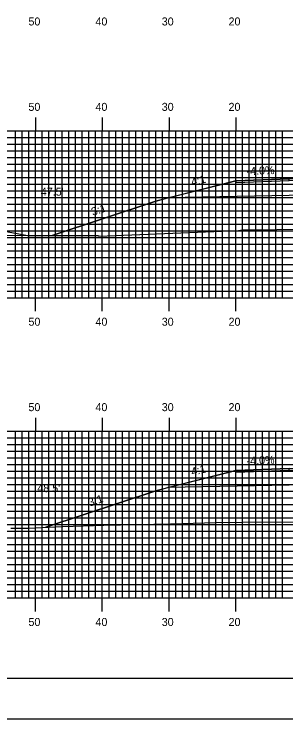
# Model space of a CAD drawing. Extents: x 1822785 to 1823129, y 442591 to 442811.
# Drawn here: x 1822898.1 to 1822938.8, y 442590.5 to 442696.2 of the extents above; entities that cross this region are included whole.
import ezdxf

# ---------------------------------------------------------------- set-up
doc = ezdxf.new("R2010")
doc.units = 0
for name, color, linetype in [('ANNOTATION', 7, 'Continuous'), ('BORDER', 7, 'Continuous'), ('D_Roadway_Centerline', 7, 'Continuous'), ('D_Roadway_Edge_Shoulder', 7, 'Continuous'), ('D_Roadway_SlopeLines', 7, 'Continuous'), ('D_Roadway_SubGrade', 7, 'Continuous'), ('D_Text_Standard', 7, 'Continuous'), ('H_V ANNOTATION', 7, 'Continuous'), ('MAJOR', 7, 'Continuous'), ('MINOR', 7, 'Continuous'), ('PLOT BOUNDARY', 7, 'Continuous'), ('S_Roadway_Centerline', 7, 'Continuous')]:
    doc.layers.add(name, color=color, linetype=linetype)

msp = doc.modelspace()

# ---------------------------------------------------------------- linework, layer by layer
at = {"layer": 'ANNOTATION'}
msp.add_line((1822903.76, 442662.99), (1822811.28, 442662.53), dxfattribs=at)
at = {"layer": 'BORDER'}
msp.add_lwpolyline([(1822801.68, 442596.67), (1823121.68, 442596.67), (1823121.68, 442806.67), (1822801.68, 442806.67)], close=True, dxfattribs=at)
at = {"layer": 'D_Roadway_Centerline'}
for points in [[(1822903.76, 442662.99), (1822919.28, 442668.16), (1822921.11, 442668.62), (1822931.28, 442671.16), (1822939.28, 442671.48), (1822951.28, 442671.72), (1822963.28, 442671.48), (1822971.28, 442671.16), (1822981.46, 442668.62), (1822998.04, 442664.47)], [(1822902.83, 442619.27), (1822919.28, 442624.75), (1822921.11, 442625.21), (1822931.28, 442627.75), (1822939.28, 442628.07), (1822951.28, 442628.31), (1822963.28, 442628.07), (1822971.28, 442627.75), (1822981.46, 442625.21), (1823001.12, 442620.29)]]:
    msp.add_lwpolyline(points, dxfattribs=at)
at = {"layer": 'D_Roadway_Edge_Shoulder'}
for points in [[(1822939.28, 442671.48), (1822931.28, 442671.16), (1822931.28, 442670.91), (1822939.28, 442671.23)], [(1822939.28, 442628.07), (1822931.28, 442627.75), (1822931.28, 442627.5), (1822939.28, 442627.82)]]:
    msp.add_lwpolyline(points, close=True, dxfattribs=at)
at = {"layer": 'D_Roadway_SlopeLines'}
for points in [[(1822931.28, 442671.16), (1822919.28, 442668.16), (1822903.76, 442662.99)], [(1822931.28, 442627.75), (1822919.28, 442624.75), (1822902.83, 442619.27)]]:
    msp.add_lwpolyline(points, dxfattribs=at)
at = {"layer": 'D_Roadway_SubGrade'}
for points in [[(1822939.28, 442668.98), (1822921.11, 442668.62), (1822931.28, 442671.16), (1822931.28, 442670.91), (1822939.28, 442671.23), (1822951.28, 442671.47), (1822963.28, 442671.23), (1822971.28, 442670.91), (1822971.28, 442671.16), (1822981.46, 442668.62), (1822963.28, 442668.98), (1822951.28, 442669.22)], [(1822939.28, 442625.57), (1822921.11, 442625.21), (1822931.28, 442627.75), (1822931.28, 442627.5), (1822939.28, 442627.82), (1822951.28, 442628.06), (1822963.28, 442627.82), (1822971.28, 442627.5), (1822971.28, 442627.75), (1822981.46, 442625.21), (1822963.28, 442625.57), (1822951.28, 442625.81)]]:
    msp.add_lwpolyline(points, close=True, dxfattribs=at)
at = {"layer": 'MAJOR'}
for p, q in [((1822901.28, 442680.67), (1822901.28, 442678.67)), ((1822911.28, 442680.67), (1822911.28, 442678.67)), ((1822921.28, 442680.67), (1822921.28, 442678.67)), ((1822931.28, 442680.67), (1822931.28, 442678.67)), ((1822811.28, 442678.67), (1823091.28, 442678.67)), ((1822811.28, 442678.67), (1823091.28, 442678.67)), ((1822901.28, 442653.67), (1822901.28, 442678.67)), ((1822911.28, 442653.67), (1822911.28, 442678.67)), ((1822921.28, 442653.67), (1822921.28, 442678.67)), ((1822931.28, 442653.67), (1822931.28, 442678.67)), ((1822811.28, 442673.67), (1823091.28, 442673.67)), ((1822811.28, 442668.67), (1823091.28, 442668.67)), ((1822811.28, 442663.67), (1823091.28, 442663.67)), ((1822811.28, 442658.67), (1823091.28, 442658.67)), ((1822811.28, 442653.67), (1823091.28, 442653.67)), ((1822811.28, 442653.67), (1823091.28, 442653.67)), ((1822901.28, 442651.66), (1822901.28, 442653.67)), ((1822911.28, 442651.66), (1822911.28, 442653.67)), ((1822921.28, 442651.66), (1822921.28, 442653.67)), ((1822931.28, 442651.66), (1822931.28, 442653.67)), ((1822901.28, 442635.67), (1822901.28, 442633.67)), ((1822911.28, 442635.67), (1822911.28, 442633.67)), ((1822921.28, 442635.67), (1822921.28, 442633.67)), ((1822931.28, 442635.67), (1822931.28, 442633.67)), ((1822811.28, 442633.67), (1823091.28, 442633.67)), ((1822811.28, 442633.67), (1823091.28, 442633.67)), ((1822901.28, 442608.67), (1822901.28, 442633.67)), ((1822911.28, 442608.67), (1822911.28, 442633.67)), ((1822921.28, 442608.67), (1822921.28, 442633.67)), ((1822931.28, 442608.67), (1822931.28, 442633.67)), ((1822811.28, 442628.67), (1823091.28, 442628.67)), ((1822811.28, 442623.67), (1823091.28, 442623.67)), ((1822811.28, 442618.67), (1823091.28, 442618.67)), ((1822811.28, 442613.67), (1823091.28, 442613.67)), ((1822811.28, 442608.67), (1823091.28, 442608.67)), ((1822811.28, 442608.67), (1823091.28, 442608.67)), ((1822901.28, 442606.66), (1822901.28, 442608.67)), ((1822911.28, 442606.66), (1822911.28, 442608.67)), ((1822921.28, 442606.66), (1822921.28, 442608.67)), ((1822931.28, 442606.66), (1822931.28, 442608.67))]:
    msp.add_line(p, q, dxfattribs=at)
at = {"layer": 'MINOR'}
for p, q in [((1822898.28, 442653.67), (1822898.28, 442678.67)), ((1822899.28, 442653.67), (1822899.28, 442678.67)), ((1822900.28, 442653.67), (1822900.28, 442678.67)), ((1822902.28, 442653.67), (1822902.28, 442678.67)), ((1822903.28, 442653.67), (1822903.28, 442678.67)), ((1822904.28, 442653.67), (1822904.28, 442678.67)), ((1822905.28, 442653.67), (1822905.28, 442678.67)), ((1822906.28, 442653.67), (1822906.28, 442678.67)), ((1822907.28, 442653.67), (1822907.28, 442678.67)), ((1822908.28, 442653.67), (1822908.28, 442678.67)), ((1822909.28, 442653.67), (1822909.28, 442678.67)), ((1822910.28, 442653.67), (1822910.28, 442678.67)), ((1822912.28, 442653.67), (1822912.28, 442678.67)), ((1822913.28, 442653.67), (1822913.28, 442678.67)), ((1822914.28, 442653.67), (1822914.28, 442678.67)), ((1822915.28, 442653.67), (1822915.28, 442678.67)), ((1822916.28, 442653.67), (1822916.28, 442678.67)), ((1822917.28, 442653.67), (1822917.28, 442678.67)), ((1822918.28, 442653.67), (1822918.28, 442678.67)), ((1822919.28, 442653.67), (1822919.28, 442678.67)), ((1822920.28, 442653.67), (1822920.28, 442678.67)), ((1822922.28, 442653.67), (1822922.28, 442678.67)), ((1822923.28, 442653.67), (1822923.28, 442678.67)), ((1822924.28, 442653.67), (1822924.28, 442678.67)), ((1822925.28, 442653.67), (1822925.28, 442678.67)), ((1822926.28, 442653.67), (1822926.28, 442678.67)), ((1822927.28, 442653.67), (1822927.28, 442678.67)), ((1822928.28, 442653.67), (1822928.28, 442678.67)), ((1822929.28, 442653.67), (1822929.28, 442678.67)), ((1822930.28, 442653.67), (1822930.28, 442678.67)), ((1822932.28, 442653.67), (1822932.28, 442678.67)), ((1822933.28, 442653.67), (1822933.28, 442678.67)), ((1822934.28, 442653.67), (1822934.28, 442678.67)), ((1822935.28, 442653.67), (1822935.28, 442678.67)), ((1822936.28, 442653.67), (1822936.28, 442678.67)), ((1822937.28, 442653.67), (1822937.28, 442678.67)), ((1822938.28, 442653.67), (1822938.28, 442678.67)), ((1822811.28, 442677.67), (1823091.28, 442677.67)), ((1822811.28, 442676.67), (1823091.28, 442676.67)), ((1822811.28, 442675.67), (1823091.28, 442675.67)), ((1822811.28, 442674.67), (1823091.28, 442674.67)), ((1822811.28, 442672.67), (1823091.28, 442672.67)), ((1822811.28, 442671.67), (1823091.28, 442671.67)), ((1822811.28, 442670.67), (1823091.28, 442670.67)), ((1822811.28, 442669.67), (1823091.28, 442669.67)), ((1822811.28, 442667.67), (1823091.28, 442667.67)), ((1822811.28, 442666.67), (1823091.28, 442666.67)), ((1822811.28, 442665.67), (1823091.28, 442665.67)), ((1822811.28, 442664.67), (1823091.28, 442664.67)), ((1822811.28, 442662.67), (1823091.28, 442662.67)), ((1822811.28, 442661.67), (1823091.28, 442661.67)), ((1822811.28, 442660.67), (1823091.28, 442660.67)), ((1822811.28, 442659.67), (1823091.28, 442659.67)), ((1822811.28, 442657.67), (1823091.28, 442657.67)), ((1822811.28, 442656.67), (1823091.28, 442656.67)), ((1822811.28, 442655.67), (1823091.28, 442655.67)), ((1822811.28, 442654.67), (1823091.28, 442654.67)), ((1822898.28, 442608.67), (1822898.28, 442633.67)), ((1822899.28, 442608.67), (1822899.28, 442633.67)), ((1822900.28, 442608.67), (1822900.28, 442633.67)), ((1822902.28, 442608.67), (1822902.28, 442633.67)), ((1822903.28, 442608.67), (1822903.28, 442633.67)), ((1822904.28, 442608.67), (1822904.28, 442633.67)), ((1822905.28, 442608.67), (1822905.28, 442633.67)), ((1822906.28, 442608.67), (1822906.28, 442633.67)), ((1822907.28, 442608.67), (1822907.28, 442633.67)), ((1822908.28, 442608.67), (1822908.28, 442633.67)), ((1822909.28, 442608.67), (1822909.28, 442633.67)), ((1822910.28, 442608.67), (1822910.28, 442633.67)), ((1822912.28, 442608.67), (1822912.28, 442633.67)), ((1822913.28, 442608.67), (1822913.28, 442633.67)), ((1822914.28, 442608.67), (1822914.28, 442633.67)), ((1822915.28, 442608.67), (1822915.28, 442633.67)), ((1822916.28, 442608.67), (1822916.28, 442633.67)), ((1822917.28, 442608.67), (1822917.28, 442633.67)), ((1822918.28, 442608.67), (1822918.28, 442633.67)), ((1822919.28, 442608.67), (1822919.28, 442633.67)), ((1822920.28, 442608.67), (1822920.28, 442633.67)), ((1822922.28, 442608.67), (1822922.28, 442633.67)), ((1822923.28, 442608.67), (1822923.28, 442633.67)), ((1822924.28, 442608.67), (1822924.28, 442633.67)), ((1822925.28, 442608.67), (1822925.28, 442633.67)), ((1822926.28, 442608.67), (1822926.28, 442633.67)), ((1822927.28, 442608.67), (1822927.28, 442633.67)), ((1822928.28, 442608.67), (1822928.28, 442633.67)), ((1822929.28, 442608.67), (1822929.28, 442633.67)), ((1822930.28, 442608.67), (1822930.28, 442633.67)), ((1822932.28, 442608.67), (1822932.28, 442633.67)), ((1822933.28, 442608.67), (1822933.28, 442633.67)), ((1822934.28, 442608.67), (1822934.28, 442633.67)), ((1822935.28, 442608.67), (1822935.28, 442633.67)), ((1822936.28, 442608.67), (1822936.28, 442633.67)), ((1822937.28, 442608.67), (1822937.28, 442633.67)), ((1822938.28, 442608.67), (1822938.28, 442633.67)), ((1822811.28, 442632.67), (1823091.28, 442632.67)), ((1822811.28, 442631.67), (1823091.28, 442631.67)), ((1822811.28, 442630.67), (1823091.28, 442630.67)), ((1822811.28, 442629.67), (1823091.28, 442629.67)), ((1822811.28, 442627.67), (1823091.28, 442627.67)), ((1822811.28, 442626.67), (1823091.28, 442626.67)), ((1822811.28, 442625.67), (1823091.28, 442625.67)), ((1822811.28, 442624.67), (1823091.28, 442624.67)), ((1822811.28, 442622.67), (1823091.28, 442622.67)), ((1822811.28, 442621.67), (1823091.28, 442621.67)), ((1822811.28, 442620.67), (1823091.28, 442620.67)), ((1822811.28, 442619.67), (1823091.28, 442619.67)), ((1822811.28, 442617.67), (1823091.28, 442617.67)), ((1822811.28, 442616.67), (1823091.28, 442616.67)), ((1822811.28, 442615.67), (1823091.28, 442615.67)), ((1822811.28, 442614.67), (1823091.28, 442614.67)), ((1822811.28, 442612.67), (1823091.28, 442612.67)), ((1822811.28, 442611.67), (1823091.28, 442611.67)), ((1822811.28, 442610.67), (1823091.28, 442610.67)), ((1822811.28, 442609.67), (1823091.28, 442609.67))]:
    msp.add_line(p, q, dxfattribs=at)
at = {"layer": 'PLOT BOUNDARY'}
msp.add_lwpolyline([(1822785.5, 442590.55), (1823125.5, 442590.55), (1823125.5, 442810.55), (1822785.5, 442810.55)], close=True, dxfattribs=at)
at = {"layer": 'S_Roadway_Centerline'}
for points in [[(1822896.35, 442663.67), (1822899.55, 442663.09), (1822900.08, 442663.01), (1822900.21, 442663), (1822901.21, 442662.99), (1822910.69, 442662.97), (1822910.77, 442662.9), (1822931.67, 442663.75), (1822932.25, 442663.82), (1822933.55, 442663.86), (1822945.21, 442664.01), (1822948.74, 442664.06), (1822949.55, 442664.07), (1822962.02, 442664.3), (1822966.67, 442664.36), (1822975.75, 442664.19), (1822983.42, 442664.35), (1822988.9, 442664.44), (1823000.16, 442664.48), (1823006.05, 442664.59)], [(1822897.57, 442619.14), (1822900.15, 442619.12), (1822905.36, 442619.4), (1822911.52, 442619.6), (1822921.49, 442619.78), (1822928.3, 442619.99), (1822932.35, 442620.05), (1822945.24, 442620.07), (1822949.76, 442620.06), (1822959.75, 442620.04), (1822962.6, 442620.07), (1822973.3, 442620.28), (1822979.45, 442620.33), (1822990.81, 442620.28), (1822996.89, 442620.26), (1823000.09, 442620.26), (1823013.45, 442620.66)]]:
    msp.add_lwpolyline(points, dxfattribs=at)

# ---------------------------------------------------------------- texts
at = {"layer": 'ANNOTATION'}
for s, rotation, p in [('-4.0%', 2.2906, (1822932.91, 442672.03)), ('4:1', 14.0362, (1822924.73, 442670.39)), ('3:1', 18.4348, (1822909.86, 442665.93)), ('-4.0%', 2.2906, (1822932.91, 442628.62)), ('4:1', 14.0362, (1822924.73, 442626.97)), ('3:1', 18.4348, (1822909.4, 442622.36))]:
    msp.add_text(s, height=1.2, rotation=rotation, dxfattribs=at).set_placement(p)
at = {"layer": 'D_Text_Standard'}
for s, p in [("47.5'", (1822902.06, 442668.96)), ("48.5'", (1822901.54, 442624.53))]:
    msp.add_text(s, height=1.2, dxfattribs=at).set_placement(p)
at = {"layer": 'H_V ANNOTATION'}
for s, p in [('50', (1822900.21, 442694.47)), ('40', (1822910.25, 442694.47)), ('30', (1822920.18, 442694.47)), ('20', (1822930.19, 442694.47)), ('50', (1822900.21, 442681.67)), ('40', (1822910.25, 442681.67)), ('30', (1822920.18, 442681.67)), ('20', (1822930.19, 442681.67)), ('50', (1822900.21, 442649.47)), ('40', (1822910.25, 442649.47)), ('30', (1822920.18, 442649.47)), ('20', (1822930.19, 442649.47)), ('50', (1822900.21, 442636.67)), ('40', (1822910.25, 442636.67)), ('30', (1822920.18, 442636.67)), ('20', (1822930.19, 442636.67)), ('50', (1822900.21, 442604.47)), ('40', (1822910.25, 442604.47)), ('30', (1822920.18, 442604.47)), ('20', (1822930.19, 442604.47))]:
    msp.add_text(s, height=1.2, dxfattribs=at).set_placement(p)

doc.saveas('drawing.dxf')
